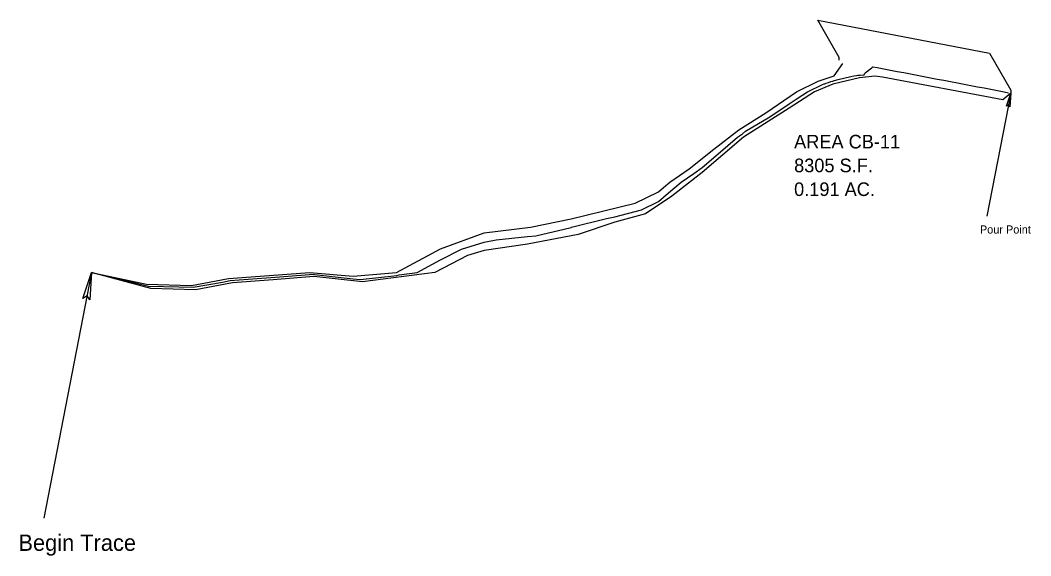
# Model space of a CAD drawing. Extents: x 2763 to 3506, y 2724 to 3118.
import ezdxf

# ---------------------------------------------------------------- set-up
doc = ezdxf.new("R2010")
doc.units = 0
for name, color, linetype in [('Default', 7, 'Continuous'), ('DESIGN - SCRATCH - User 1', 7, 'Continuous'), ('SURVEY - CENTERLINE - Preliminary', 7, 'Continuous'), ('SURVEY - CENTERLINE - Preliminary Text', 7, 'Continuous'), ('SURVEY - DRAINAGE - Area Shapes', 7, 'Continuous')]:
    doc.layers.add(name, color=color, linetype=linetype)

msp = doc.modelspace()

# ---------------------------------------------------------------- linework, layer by layer
at = {"layer": 'DESIGN - SCRATCH - User 1'}
msp.add_line((3491.6, 3064.22), (3474.06, 2973.77), dxfattribs=at)
msp.add_lwpolyline([(3491.6, 3064.22), (3490.91, 3054.11), (3489.93, 3055.63), (3488.41, 3054.6)], close=True, dxfattribs=at)
msp.add_lwpolyline([(3491.6, 3064.22), (3490.91, 3054.11), (3489.93, 3055.63), (3488.41, 3054.6), (3491.6, 3064.22)], dxfattribs=at)
at = {"layer": 'SURVEY - CENTERLINE - Preliminary'}
msp.add_lwpolyline([(2815.39, 2932.32), (2847.47, 2924.74), (2857.23, 2922.22), (2879.54, 2921.62), (2890.17, 2921.32), (2911.62, 2925.16), (2917.32, 2926.43), (2943.7, 2928.3), (2947.33, 2928.56), (2975.77, 2930.83), (2977.1, 2930.95), (3007.85, 2927.68), (3012.87, 2927.12), (3039.93, 2930.1), (3041.74, 2930.44), (3054.79, 2932.32), (3066.2, 2938.33), (3072.01, 2941.56), (3087.47, 2949.5), (3104.08, 2954.47), (3113.02, 2956.26), (3136.16, 2958.66), (3142.14, 2959.32), (3168.24, 2965.44), (3168.29, 2965.45), (3168.42, 2965.51), (3194.19, 2971.85), (3200.31, 2973.12), (3219.93, 2978.4), (3232.39, 2984.53), (3239.91, 2990.91), (3249.09, 2998.69), (3258.33, 3005.05), (3264.47, 3009.59), (3276.31, 3019.63), (3290.61, 3031.88), (3294.21, 3034.29), (3296.54, 3036.09), (3314.37, 3046.63), (3328.62, 3056.41), (3333.83, 3059.68), (3342.03, 3065.07), (3353.11, 3070.55), (3354.25, 3070.94), (3354.83, 3071.14), (3355.75, 3071.45), (3357.42, 3072.03), (3359.23, 3072.62), (3360.7, 3073.1), (3361.61, 3073.39), (3361.85, 3073.45), (3364.71, 3074.16), (3373.93, 3076.31), (3376.19, 3076.84), (3378.12, 3077.21), (3378.99, 3077.38), (3380.76, 3077.5), (3383.7, 3077.69), (3383.87, 3077.84), (3383.88, 3077.85), (3383.9, 3077.86), (3383.9, 3077.87), (3383.9, 3077.87), (3383.9, 3077.87), (3383.92, 3077.87), (3383.98, 3077.94), (3384.11, 3078.47), (3384.15, 3078.67), (3384.59, 3079.02), (3385.18, 3079.49), (3388.05, 3081.79), (3389.04, 3082.58), (3389.8, 3083.19), (3390, 3083.49), (3390.09, 3083.64), (3390.09, 3083.64), (3390.09, 3083.64), (3393.38, 3083.01), (3398.29, 3082.07), (3403.2, 3081.13), (3408.11, 3080.19), (3413.02, 3079.25), (3417.93, 3078.31), (3422.84, 3077.37), (3427.75, 3076.43), (3432.67, 3075.49), (3437.58, 3074.55), (3442.49, 3073.62), (3447.4, 3072.68), (3452.31, 3071.74), (3457.22, 3070.8), (3462.13, 3069.86), (3467.04, 3068.92), (3471.95, 3067.98), (3476.86, 3067.04), (3481.77, 3066.1), (3486.69, 3065.16), (3490.05, 3064.51)], dxfattribs=at)
at = {"layer": 'SURVEY - CENTERLINE - Preliminary Text'}
msp.add_line((2815.39, 2932.32), (2780.33, 2751.42), dxfattribs=at)
msp.add_lwpolyline([(2815.39, 2932.32), (2814.02, 2912.11), (2812.06, 2915.14), (2809.01, 2913.08)], close=True, dxfattribs=at)
msp.add_lwpolyline([(2815.39, 2932.32), (2814.02, 2912.11), (2812.06, 2915.14), (2809.01, 2913.08), (2815.39, 2932.32)], dxfattribs=at)
at = {"layer": 'SURVEY - DRAINAGE - Area Shapes'}
msp.add_line((3349.79, 3117.83), (3349.78, 3117.83), dxfattribs=at)
for points in [[(3349.78, 3117.83), (3475.94, 3093.68), (3491.58, 3066.26), (3491.6, 3064.22), (3485.68, 3059.27), (3397.13, 3076.03), (3391.7, 3076.61), (3380.24, 3075.46), (3360.7, 3070.87), (3347.21, 3065.07), (3328.62, 3053.06)], [(3365.45, 3088.35), (3365.44, 3090.4), (3349.79, 3117.83)], [(3168.24, 2971.67), (3215.3, 2983.18), (3232.39, 2991.58), (3236.17, 2994.79), (3240.78, 2998.69), (3255, 3008.49), (3273.18, 3022.87), (3291.49, 3037.11), (3311.36, 3049.74), (3333.99, 3065.07), (3349.84, 3072.9), (3361.66, 3076.87), (3368.05, 3085.93)], [(3328.62, 3053.06), (3295.08, 3031.88), (3264.47, 3005.79), (3242.33, 2988.41), (3222.91, 2975.32), (3200.31, 2969.24), (3173.27, 2960.3), (3136.16, 2953.1), (3104.08, 2948.44), (3091.99, 2944.83), (3067.83, 2932.32), (3014.57, 2925.37), (2978.78, 2929.2), (2949.04, 2926.79), (2919.02, 2924.66), (2891.93, 2919.5), (2858.99, 2920.4), (2815.39, 2932.32)], [(2815.39, 2932.32), (2855.84, 2923.65), (2888.79, 2922.76), (2915.98, 2927.81), (2945.99, 2929.94), (2975.77, 2932.32), (3007.85, 2929.49), (3039.69, 2932.32), (3072.01, 2949.6), (3104.08, 2961.4), (3138.34, 2965.51), (3168.24, 2971.67)]]:
    msp.add_lwpolyline(points, dxfattribs=at)

# ---------------------------------------------------------------- texts
at = {"layer": 'Default'}
for s, p in [('AREA CB-11', (3332.21, 3023.5)), ('8305 S.F.', (3332.21, 3006)), ('0.191 AC.', (3332.21, 2988.5))]:
    msp.add_text(s, height=10, dxfattribs=at).set_placement(p)
at = {"layer": 'DESIGN - SCRATCH - User 1'}
msp.add_text('Pour Point', height=6, dxfattribs=at).set_placement((3468.94, 2960.87))
at = {"layer": 'SURVEY - CENTERLINE - Preliminary Text'}
msp.add_text('Begin Trace ', height=12, dxfattribs=at).set_placement((2761.53, 2727.43))

doc.saveas('drawing.dxf')
